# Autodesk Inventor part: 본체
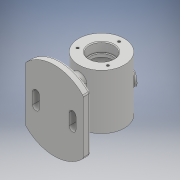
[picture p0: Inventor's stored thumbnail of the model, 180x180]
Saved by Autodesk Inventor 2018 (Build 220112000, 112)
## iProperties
Created: 2022-02
Part Number: 본체
Material: Generic
Document SubType Name: Modeling
Designer: 1class 2
Density: 1 g/cm^3
Appearance: Default
Author: 1class 2
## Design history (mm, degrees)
sketch "스케치1"
  geometry: L1 (38, 54.198)-(-38, 54.198); L2 (-38, 54.198)-(-38, 35.496); L3 (-38, -54.198)-(38, -54.198); L4 (38, -54.198)-(38, -35.496); L5 (38, 54.198)-(-38, -54.198); L6 (-38, 54.198)-(38, -54.198); L7 (38, 35.496)-(38, 54.198); L8 (38, -35.496)-(38, 35.496); L9 (-38, 35.496)-(-38, -35.496); L10 (-38, -35.496)-(-38, -54.198); L11 (0, 19)-(0, -19); L12 (-7, 19)-(-7, -19); L13 (7, -19)-(7, 19); L14 (24, 7.5)-(24, -7.5); L15 (19.5, 7.5)-(19.5, -7.5); L16 (28.5, -7.5)-(28.5, 7.5); L17 (-24, 7.5)-(-24, -7.5); L18 (-28.5, 7.5)-(-28.5, -7.5); L19 (-19.5, -7.5)-(-19.5, 7.5); C1 r 42.5 at (0, 0); A1 r 52 centre (0, 0) between (-38, -35.496) and (38, -35.496); A2 r 52 centre (0, 0) between (-38, 35.496) and (-38, -35.496); A3 r 52 centre (0, 0) between (38, -35.496) and (38, 35.496); A4 r 52 centre (0, 0) between (38, 35.496) and (-38, 35.496); A5 r 7 centre (0, 19) between (7, 19) and (-7, 19); A6 r 7 centre (0, -19) between (-7, -19) and (7, -19); A7 r 4.5 centre (24, 7.5) between (28.5, 7.5) and (19.5, 7.5); A8 r 4.5 centre (24, -7.5) between (19.5, -7.5) and (28.5, -7.5); A9 r 4.5 centre (-24, 7.5) between (-19.5, 7.5) and (-28.5, 7.5); A10 r 4.5 centre (-24, -7.5) between (-28.5, -7.5) and (-19.5, -7.5); 6 further points
  constraints: 44 end point, 20 point on circle, 14 parallel, 12 tangent, 11 centre point, 7 midpoint, 4 coincident, 3 perpendicular, 1 horizontal, 1 horizontal alignment, 1 point on line, 1 vertical, 1 vertical alignment
  dimensions: "d0" = 104 diameter of A1; "d1" = 76 distance of L3.end L3.start; "d2" = 18.70114 distance of L3.end L4.end; "d3" = 38 distance of L11.start L11.end; "d4" = 14 diameter of A6; "d5" = 15 distance of L14.start L14.end; "d6" = 9 diameter of A8; "d7" = 15 distance of L17.start L17.end; "d8" = 9 diameter of A10; "d9" = 48 distance of point (-24, 0) point (24, 0); "d10" = 24 distance of A1.centre point (24, 0); "d11" = 24 distance of point (0, 0) point (-24, 0); "d53" = 85 diameter of C1
extrude "돌출1" new body sketch "스케치1" distance "d12" = 10; taper "d13" = 0 deg
extrude "돌출2" join sketch "스케치1" distance "d14" = 40; taper "d15" = 0 deg
sketch "스케치2"
  geometry: L1 (38, 0)-(-38, 0) reference; C1 r 30 at (0, 62); 1 further point
  constraints: 1 centre point, 1 vertical alignment
  dimensions: "d16" = 60 diameter of C1; "d17" = 62 vertical distance of C1.centre L1.start
extrude "돌출3" join sketch "스케치2" stored distance "d18" = 72; taper "d19" = 0 deg
sketch "스케치6"
  geometry: L1 (0, 62)-(16.5, 90.579); L2 (0, 62)-(0, 92); L3 (19.476, 87.734)-(15.621, 81.056); L4 (22.941, 85.734)-(18.388, 77.849); L5 (19.476, 87.734)-(22.941, 85.734); L6 (15.621, 81.056)-(18.388, 77.849); 1 further point
  constraints: 12 end point, 1 parallel, 1 vertical
  dimensions: "d55" = 33 distance of L1.start L1.end; "d56" = 30 deg angle of L2 L1; "d58" = 8 diameter of L3 L1; "d60" = 16 diameter of L4 L1; "d61" = 3.46448 horizontal distance of L3.start L4.start
revolve "회전2" stored, may be unused: angle "d62" = 90 deg
sketch "스케치3"
  geometry: L1 (92, -36)-(92, 36) reference; L2 (92, 36)-(32, 36) reference; L3 (32, -36)-(92, -36) reference; L4 (32, -36)-(32, 36) reference; L5 (78, 36)-(78, 24.3); L6 (77.7, 24)-(76, 24); L7 (76, 24)-(76, 20); L8 (76, 20)-(84, 20); L9 (87, 17)-(87, -17); L10 (84, -20)-(76, -20); L11 (76, -20)-(76, -24); L12 (76, -24)-(77.7, -24); L13 (78, -24.3)-(78, -36); L14 (62, 36)-(62, -36); A1 r 0.3 centre (77.7, 24.3) between (77.7, 24) and (78, 24.3); A2 r 0.3 centre (77.7, -24.3) between (78, -24.3) and (77.7, -24); A3 r 3 centre (84, 17) between (87, 17) and (84, 20); A4 r 3 centre (84, -17) between (84, -20) and (87, -17); 5 further points
  constraints: 20 end point, 14 point on line, 8 point on circle, 8 tangent, 6 perpendicular, 4 centre point, 2 equal radius, 2 midpoint, 1 vertical
  dimensions: "d20" = 50 diameter of L9 L14; "d21" = 32 diameter of L5 L14; "d22" = 28 diameter of L7 L14; "d23" = 40 distance of point (87, 20) point (87, -20); "d24" = 12 distance of L5.start point (78, 24); "d25" = 12 distance of point (78, -24) L13.end; "d26" = 4 distance of L6.end L7.end; "d28" = 0.3 radius of A1; "d74" = 3 radius of A3
revolve "회전1" sketch "스케치3" stored, may be unused: angle "d27" = 90 deg
sketch "스케치4" dims "d29" = 46
  geometry: C1 r 30 at (0, 0) reference; 5 further points
  constraints: 2 coincident, 2 vertical alignment, 6 other
  dimensions: "d32" = 360 deg dimension on point (0, 0) point (0, 23) (derived)
hole "구멍1" sketch "스케치4" at (0, 23), (-19.919, -11.5), (19.919, -11.5) diameter "d34" = 3.242; stored, may be unused: countersink angle "d38" = 90 deg, drill point angle "d40" = 118 deg; dims "d35" = 8, "d36" = 4, "d37" = 2, "d39" = 10
sketch "스케치5"
  geometry: C1 r 16 at (0, 0) reference; C2 r 30 at (0, 0) reference; C3 r 23 at (0, 0); C4 r 1.621 at (0, 23) reference; 4 further points
  constraints: 2 coincident, 1 centre point, 1 vertical alignment, 4 other
  dimensions: "d41" = 46 diameter of C3; "d44" = 360 deg dimension on C3.centre point (0, 23) (derived)
hole "구멍2" sketch "스케치5" at (0, 23), (-19.919, -11.5), (19.919, -11.5) diameter "d46" = 3.242; stored, may be unused: countersink angle "d50" = 90 deg, drill point angle "d52" = 118 deg; dims "d47" = 8, "d48" = 4, "d49" = 2, "d51" = 10
sketch "스케치8"
  geometry: 1 further point
sketch "스케치9"
  geometry: C1 r 42.5 at (0, 0); 1 further point
  constraints: 1 centre point, 1 coincident, 1 other
  dimensions: "d63" = 85 diameter of C1
feature "엠보싱1" sketch "스케치9" dims "d64" = 0.5, "d65" = 0
fillet "모깎기1" dims "d66" = 3
fillet "모깎기2" dims "d67" = 3
chamfer "모따기1" distance "d69" = 1; stored, may be unused: second distance "d70" = 2, angle "d71" = 45 deg
sketch "스케치10"
  geometry: L1 (12.548, 91.734)-(19.476, 87.734) reference; L2 (16.012, 89.734)-(19.476, 87.734); L3 (19.476, 87.734)-(15.55, 80.933); L4 (15.55, 80.933)-(12.086, 82.933); L5 (12.086, 82.933)-(16.012, 89.734); 1 further point
  constraints: 8 end point, 3 perpendicular, 1 collinear, 1 midpoint
revolve "회전3" sketch "스케치10" stored, may be unused: angle "d72" = 90 deg
fillet "모깎기4" dims "d73" = 1
node "솔리드1"
node "투영된 루프1"
